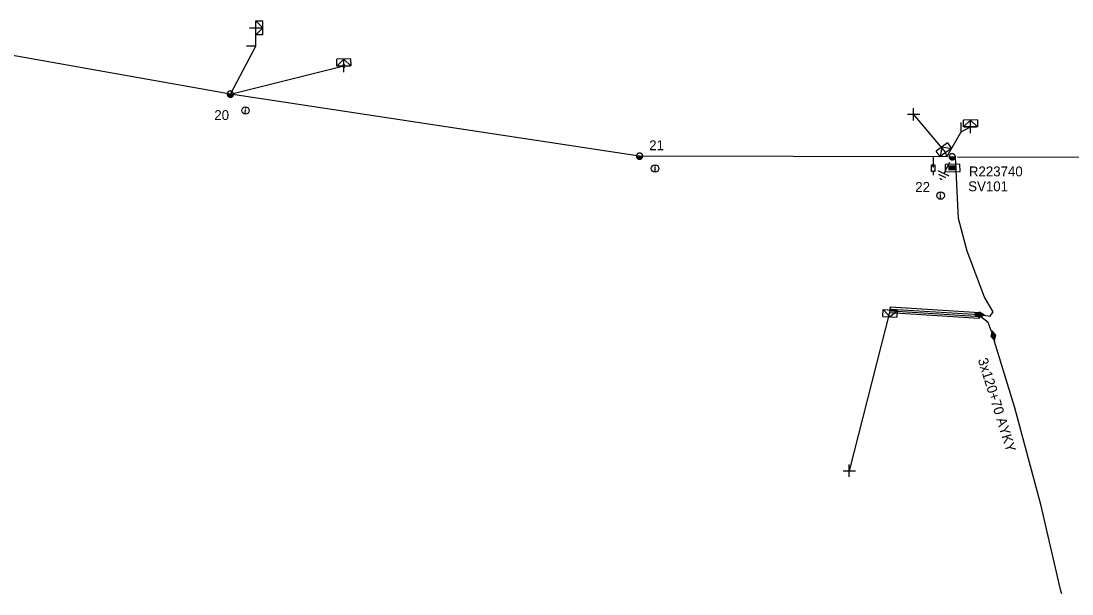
# Model space of a CAD drawing. Extents: x -544780 to -541582, y -1198995 to -1196551.
# Drawn here: x -541850 to -541744, y -1198987.6 to -1198929.8 of the extents above; entities that cross this region are included whole.
import ezdxf

# ---------------------------------------------------------------- set-up
doc = ezdxf.new("R2010")
doc.units = 0
for name, color, linetype in [('Vrstva 1', 7, 'Continuous'), ('Vrstva 10', 7, 'Continuous'), ('Vrstva 13', 7, 'Continuous'), ('Vrstva 14', 7, 'Continuous'), ('Vrstva 15', 7, 'Continuous'), ('Vrstva 16', 7, 'Continuous'), ('Vrstva 19', 7, 'Continuous'), ('Vrstva 2', 7, 'Continuous'), ('Vrstva 20', 7, 'Continuous'), ('Vrstva 28', 7, 'Continuous'), ('Vrstva 29', 7, 'Continuous'), ('Vrstva 30', 7, 'Continuous'), ('Vrstva 31', 7, 'Continuous'), ('Vrstva 34', 7, 'Continuous'), ('Vrstva 36', 7, 'Continuous'), ('Vrstva 4', 7, 'Continuous'), ('Vrstva 5', 7, 'Continuous'), ('Vrstva 54', 7, 'Continuous'), ('Vrstva 59', 7, 'Continuous'), ('Vrstva 6', 7, 'Continuous'), ('Vrstva 8', 7, 'Continuous'), ('Vrstva 9', 7, 'Continuous')]:
    doc.layers.add(name, color=color, linetype=linetype)

# ---------------------------------------------------------------- blocks, each defined once
blk = doc.blocks.new('NN440')
at = {"layer": 'Vrstva 2'}
for points in [[(0.63, 0), (0.63, 0.06), (0.62, 0.13), (0.6, 0.19), (0.58, 0.25), (0.55, 0.31), (0.51, 0.37), (0.47, 0.42), (0.42, 0.46), (0.37, 0.51), (0.32, 0.54), (0.26, 0.57), (0.2, 0.59), (0.13, 0.61), (0.07, 0.62), (0, 0.63), (-0.06, 0.62), (-0.13, 0.61), (-0.19, 0.59), (-0.26, 0.57), (-0.31, 0.54), (-0.37, 0.51), (-0.42, 0.46), (-0.47, 0.42), (-0.51, 0.37), (-0.54, 0.31), (-0.57, 0.25), (-0.6, 0.19), (-0.62, 0.13), (-0.63, 0.06), (-0.63, 0), (-0.63, -0.07), (-0.62, -0.14), (-0.6, -0.2), (-0.57, -0.26), (-0.54, -0.32), (-0.51, -0.37), (-0.47, -0.43), (-0.42, -0.47), (-0.37, -0.51), (-0.31, -0.55), (-0.26, -0.58), (-0.19, -0.6), (-0.13, -0.62), (-0.06, -0.63), (0, -0.63), (0.07, -0.63), (0.13, -0.62), (0.2, -0.6), (0.26, -0.58), (0.32, -0.55), (0.37, -0.51), (0.42, -0.47), (0.47, -0.43), (0.51, -0.37), (0.55, -0.32), (0.58, -0.26), (0.6, -0.2), (0.62, -0.14), (0.63, -0.07), (0.63, 0)], [(-0.63, 0), (0.63, 0)], [(-0.6, -0.18), (0.57, -0.18)], [(-0.51, -0.32), (0.5, -0.32)], [(-0.37, -0.47), (0.35, -0.47)]]:
    blk.add_lwpolyline(points, dxfattribs=at)
blk = doc.blocks.new('NN770')
at = {"layer": 'Vrstva 10'}
for p, q in [((0, 0.19), (0, 0.26)), ((0, -0.28), (0, 0.11))]:
    blk.add_line(p, q, dxfattribs=at)
blk.add_circle((0, -0.01), 0.375, dxfattribs=at)
blk = doc.blocks.new('NN870')
at = {"layer": 'Vrstva 4'}
for points in [[(0, -0.25), (0.5, 0), (0, 0.25), (-0.5, 0), (0, -0.25)], [(0.37, 0), (0, 0.19), (-0.36, 0), (0, -0.19), (0.37, 0)], [(0.24, 0), (0, 0.12), (-0.25, 0), (0, -0.12), (0.24, 0)], [(0.12, 0), (0, 0.06), (-0.13, 0), (0, -0.06), (0.12, 0)]]:
    blk.add_lwpolyline(points, dxfattribs=at)
blk = doc.blocks.new('NN800')
at = {"layer": 'Vrstva 1'}
for points in [[(-0.44, 0.44), (0.44, -0.44)], [(-0.44, -0.44), (0.44, 0.44)]]:
    blk.add_lwpolyline(points, dxfattribs=at)
blk = doc.blocks.new('NN820')
at = {"layer": 'Vrstva 13'}
for points in [[(0, 0), (0, -1.05)], [(-0.16, -0.81), (0.16, -0.81)], [(-0.16, -1.47), (-0.16, -0.81)], [(0, -1.05), (-0.06, -0.93)], [(0, -1.05), (0.06, -0.93)], [(0.16, -0.81), (0.16, -1.47)], [(0.16, -1.47), (-0.16, -1.47)], [(0, -1.47), (0, -1.87)]]:
    blk.add_lwpolyline(points, dxfattribs=at)
blk = doc.blocks.new('NN620')
at = {"layer": 'Vrstva 8'}
for points in [[(0.75, 0), (-0.75, 0)], [(-0.75, 0), (-0.75, -0.75)], [(0.75, -0.75), (0.75, 0)], [(-0.75, -0.75), (0.75, -0.75)], [(0.37, -0.18), (-0.38, -0.18)], [(-0.38, -0.18), (-0.38, -0.56)], [(-0.38, -0.56), (0.37, -0.56)], [(0.32, -0.23), (-0.33, -0.23)], [(-0.33, -0.23), (-0.33, -0.51)], [(-0.33, -0.51), (0.32, -0.51)], [(0.27, -0.27), (-0.28, -0.27)], [(-0.28, -0.27), (-0.28, -0.46)], [(-0.28, -0.46), (0.27, -0.46)], [(0.23, -0.32), (-0.23, -0.32)], [(-0.23, -0.32), (-0.23, -0.42)], [(-0.23, -0.42), (0.23, -0.42)], [(-0.19, -0.37), (0.19, -0.37)], [(0.23, -0.42), (0.23, -0.32)], [(0.27, -0.46), (0.27, -0.27)], [(0.32, -0.51), (0.32, -0.23)], [(0.37, -0.56), (0.37, -0.18)]]:
    blk.add_lwpolyline(points, dxfattribs=at)
blk = doc.blocks.new('NN630')
at = {"layer": 'Vrstva 9'}
for points in [[(0, -0.7), (-0.7, 0)], [(-0.7, -0.7), (-0.7, 0), (0.7, 0), (0.7, -0.7)], [(-0.7, -0.7), (0.7, -0.7)], [(0, -0.7), (0.7, 0)]]:
    blk.add_lwpolyline(points, dxfattribs=at)
blk = doc.blocks.new('NN810')
at = {"layer": 'Vrstva 14'}
for points in [[(0, -0.64), (0, -1.89)], [(0.63, -1.89), (-0.62, -1.89)], [(0.39, -2.2), (-0.4, -2.2)], [(0, -2.52), (-0.12, -2.52)], [(0.14, -2.52), (0, -2.52)]]:
    blk.add_lwpolyline(points, dxfattribs=at)
blk = doc.blocks.new('NN500')
at = {"layer": 'Vrstva 2'}
for points in [[(0, -0.24), (0.02, -0.23), (0.05, -0.23), (0.07, -0.22), (0.09, -0.22), (0.12, -0.2), (0.14, -0.19), (0.16, -0.18), (0.17, -0.16), (0.19, -0.14), (0.2, -0.12), (0.21, -0.1), (0.22, -0.07), (0.23, -0.05), (0.23, -0.02), (0.23, 0), (0.23, 0.02), (0.23, 0.05), (0.22, 0.07), (0.21, 0.1), (0.2, 0.12), (0.19, 0.14), (0.17, 0.16), (0.16, 0.17), (0.14, 0.19), (0.12, 0.2), (0.09, 0.21), (0.07, 0.22), (0.05, 0.23), (0.02, 0.23), (0, 0.23), (-0.03, 0.23), (-0.05, 0.23), (-0.07, 0.22), (-0.1, 0.21), (-0.12, 0.2), (-0.14, 0.19), (-0.16, 0.17), (-0.18, 0.16), (-0.19, 0.14), (-0.2, 0.12), (-0.22, 0.1), (-0.22, 0.07), (-0.23, 0.05), (-0.23, 0.02), (-0.24, 0), (-0.23, -0.02), (-0.23, -0.05), (-0.22, -0.07), (-0.22, -0.1), (-0.2, -0.12), (-0.19, -0.14), (-0.18, -0.16), (-0.16, -0.18), (-0.14, -0.19), (-0.12, -0.2), (-0.1, -0.22), (-0.07, -0.22), (-0.05, -0.23), (-0.03, -0.23), (0, -0.24)], [(0, -0.24), (0.02, -0.23), (0.05, -0.23), (0.07, -0.22), (0.09, -0.22), (0.12, -0.2), (0.14, -0.19), (0.16, -0.18), (0.17, -0.16), (0.19, -0.14), (0.2, -0.12), (0.21, -0.1), (0.22, -0.07), (0.23, -0.05), (0.23, -0.02), (0.23, 0), (0.23, 0.02), (0.23, 0.05), (0.22, 0.07), (0.21, 0.1), (0.2, 0.12), (0.19, 0.14), (0.17, 0.16), (0.16, 0.17), (0.14, 0.19), (0.12, 0.2), (0.09, 0.21), (0.07, 0.22), (0.05, 0.23), (0.02, 0.23), (0, 0.23), (-0.03, 0.23), (-0.05, 0.23), (-0.07, 0.22), (-0.1, 0.21), (-0.12, 0.2), (-0.14, 0.19), (-0.16, 0.17), (-0.18, 0.16), (-0.19, 0.14), (-0.2, 0.12), (-0.22, 0.1), (-0.22, 0.07), (-0.23, 0.05), (-0.23, 0.02), (-0.24, 0), (-0.23, -0.02), (-0.23, -0.05), (-0.22, -0.07), (-0.22, -0.1), (-0.2, -0.12), (-0.19, -0.14), (-0.18, -0.16), (-0.16, -0.18), (-0.14, -0.19), (-0.12, -0.2), (-0.1, -0.22), (-0.07, -0.22), (-0.05, -0.23), (-0.03, -0.23), (0, -0.24)], [(0, -0.21), (0.02, -0.2), (0.04, -0.2), (0.06, -0.2), (0.08, -0.19), (0.1, -0.18), (0.12, -0.17), (0.14, -0.15), (0.15, -0.14), (0.16, -0.12), (0.18, -0.1), (0.19, -0.08), (0.19, -0.06), (0.2, -0.04), (0.2, -0.02), (0.2, 0), (0.2, 0.02), (0.2, 0.04), (0.19, 0.06), (0.19, 0.08), (0.18, 0.1), (0.16, 0.12), (0.15, 0.14), (0.14, 0.15), (0.12, 0.17), (0.1, 0.18), (0.08, 0.19), (0.06, 0.19), (0.04, 0.2), (0.02, 0.2), (0, 0.2), (-0.02, 0.2), (-0.04, 0.2), (-0.06, 0.19), (-0.08, 0.19), (-0.1, 0.18), (-0.12, 0.17), (-0.14, 0.15), (-0.15, 0.14), (-0.17, 0.12), (-0.18, 0.1), (-0.19, 0.08), (-0.2, 0.06), (-0.2, 0.04), (-0.21, 0.02), (-0.21, 0), (-0.21, -0.02), (-0.2, -0.04), (-0.2, -0.06), (-0.19, -0.08), (-0.18, -0.1), (-0.17, -0.12), (-0.15, -0.14), (-0.14, -0.15), (-0.12, -0.17), (-0.1, -0.18), (-0.08, -0.19), (-0.06, -0.2), (-0.04, -0.2), (-0.02, -0.2), (0, -0.21)], [(0, -0.18), (0.02, -0.18), (0.04, -0.17), (0.05, -0.17), (0.07, -0.16), (0.09, -0.15), (0.1, -0.14), (0.12, -0.13), (0.13, -0.12), (0.14, -0.1), (0.15, -0.09), (0.16, -0.07), (0.17, -0.05), (0.17, -0.04), (0.17, -0.02), (0.17, 0), (0.17, 0.02), (0.17, 0.04), (0.17, 0.05), (0.16, 0.07), (0.15, 0.09), (0.14, 0.1), (0.13, 0.12), (0.12, 0.13), (0.1, 0.14), (0.09, 0.15), (0.07, 0.16), (0.05, 0.17), (0.04, 0.17), (0.02, 0.17), (0, 0.18), (-0.02, 0.17), (-0.04, 0.17), (-0.06, 0.17), (-0.07, 0.16), (-0.09, 0.15), (-0.1, 0.14), (-0.12, 0.13), (-0.13, 0.12), (-0.14, 0.1), (-0.15, 0.09), (-0.16, 0.07), (-0.17, 0.05), (-0.17, 0.04), (-0.18, 0.02), (-0.18, 0), (-0.18, -0.02), (-0.17, -0.04), (-0.17, -0.05), (-0.16, -0.07), (-0.15, -0.09), (-0.14, -0.1), (-0.13, -0.12), (-0.12, -0.13), (-0.1, -0.14), (-0.09, -0.15), (-0.07, -0.16), (-0.06, -0.17), (-0.04, -0.17), (-0.02, -0.18), (0, -0.18)], [(0, -0.15), (0.01, -0.15), (0.03, -0.14), (0.04, -0.14), (0.06, -0.13), (0.07, -0.13), (0.08, -0.12), (0.1, -0.11), (0.11, -0.1), (0.12, -0.09), (0.13, -0.07), (0.13, -0.06), (0.14, -0.05), (0.14, -0.03), (0.14, -0.02), (0.14, 0), (0.14, 0.01), (0.14, 0.03), (0.14, 0.04), (0.13, 0.06), (0.13, 0.07), (0.12, 0.09), (0.11, 0.1), (0.1, 0.11), (0.08, 0.12), (0.07, 0.13), (0.06, 0.13), (0.04, 0.14), (0.03, 0.14), (0.01, 0.14), (0, 0.15), (-0.02, 0.14), (-0.03, 0.14), (-0.05, 0.14), (-0.06, 0.13), (-0.07, 0.13), (-0.09, 0.12), (-0.1, 0.11), (-0.11, 0.1), (-0.12, 0.09), (-0.13, 0.07), (-0.13, 0.06), (-0.14, 0.04), (-0.14, 0.03), (-0.15, 0.01), (-0.15, 0), (-0.15, -0.02), (-0.14, -0.03), (-0.14, -0.05), (-0.13, -0.06), (-0.13, -0.07), (-0.12, -0.09), (-0.11, -0.1), (-0.1, -0.11), (-0.09, -0.12), (-0.07, -0.13), (-0.06, -0.13), (-0.05, -0.14), (-0.03, -0.14), (-0.02, -0.15), (0, -0.15)], [(0, -0.12), (0.01, -0.12), (0.02, -0.11), (0.03, -0.11), (0.05, -0.11), (0.06, -0.1), (0.07, -0.09), (0.08, -0.09), (0.09, -0.08), (0.09, -0.07), (0.1, -0.06), (0.11, -0.05), (0.11, -0.04), (0.11, -0.02), (0.11, -0.01), (0.12, 0), (0.11, 0.01), (0.11, 0.02), (0.11, 0.04), (0.11, 0.05), (0.1, 0.06), (0.09, 0.07), (0.09, 0.08), (0.08, 0.09), (0.07, 0.09), (0.06, 0.1), (0.05, 0.11), (0.03, 0.11), (0.02, 0.11), (0.01, 0.12), (0, 0.12), (-0.01, 0.12), (-0.03, 0.11), (-0.04, 0.11), (-0.05, 0.11), (-0.06, 0.1), (-0.07, 0.09), (-0.08, 0.09), (-0.09, 0.08), (-0.1, 0.07), (-0.1, 0.06), (-0.11, 0.05), (-0.11, 0.04), (-0.12, 0.02), (-0.12, 0.01), (-0.12, 0), (-0.12, -0.01), (-0.12, -0.02), (-0.11, -0.04), (-0.11, -0.05), (-0.1, -0.06), (-0.1, -0.07), (-0.09, -0.08), (-0.08, -0.09), (-0.07, -0.09), (-0.06, -0.1), (-0.05, -0.11), (-0.04, -0.11), (-0.03, -0.11), (-0.01, -0.12), (0, -0.12)], [(0, -0.09), (0.01, -0.09), (0.02, -0.09), (0.03, -0.08), (0.03, -0.08), (0.04, -0.08), (0.05, -0.07), (0.06, -0.07), (0.06, -0.06), (0.07, -0.05), (0.07, -0.04), (0.08, -0.04), (0.08, -0.03), (0.08, -0.02), (0.09, -0.01), (0.09, 0), (0.09, 0.01), (0.08, 0.02), (0.08, 0.03), (0.08, 0.03), (0.07, 0.04), (0.07, 0.05), (0.06, 0.06), (0.06, 0.06), (0.05, 0.07), (0.04, 0.07), (0.03, 0.08), (0.03, 0.08), (0.02, 0.08), (0.01, 0.09), (0, 0.09), (-0.01, 0.09), (-0.02, 0.08), (-0.03, 0.08), (-0.04, 0.08), (-0.04, 0.07), (-0.05, 0.07), (-0.06, 0.06), (-0.07, 0.06), (-0.07, 0.05), (-0.08, 0.04), (-0.08, 0.03), (-0.08, 0.03), (-0.09, 0.02), (-0.09, 0.01), (-0.09, 0), (-0.09, -0.01), (-0.09, -0.02), (-0.08, -0.03), (-0.08, -0.04), (-0.08, -0.04), (-0.07, -0.05), (-0.07, -0.06), (-0.06, -0.07), (-0.05, -0.07), (-0.04, -0.08), (-0.04, -0.08), (-0.03, -0.08), (-0.02, -0.09), (-0.01, -0.09), (0, -0.09)], [(0, -0.06), (0, -0.06), (0.01, -0.06), (0.02, -0.05), (0.02, -0.05), (0.03, -0.05), (0.03, -0.05), (0.04, -0.04), (0.04, -0.04), (0.05, -0.03), (0.05, -0.03), (0.05, -0.02), (0.05, -0.02), (0.05, -0.01), (0.06, -0.01), (0.06, 0), (0.06, 0.01), (0.05, 0.01), (0.05, 0.02), (0.05, 0.02), (0.05, 0.03), (0.05, 0.03), (0.04, 0.04), (0.04, 0.04), (0.03, 0.05), (0.03, 0.05), (0.02, 0.05), (0.02, 0.05), (0.01, 0.06), (0, 0.06), (0, 0.06), (-0.01, 0.06), (-0.01, 0.06), (-0.02, 0.05), (-0.02, 0.05), (-0.03, 0.05), (-0.03, 0.05), (-0.04, 0.04), (-0.04, 0.04), (-0.05, 0.03), (-0.05, 0.03), (-0.05, 0.02), (-0.06, 0.02), (-0.06, 0.01), (-0.06, 0.01), (-0.06, 0), (-0.06, -0.01), (-0.06, -0.01), (-0.06, -0.02), (-0.05, -0.02), (-0.05, -0.03), (-0.05, -0.03), (-0.04, -0.04), (-0.04, -0.04), (-0.03, -0.05), (-0.03, -0.05), (-0.02, -0.05), (-0.02, -0.05), (-0.01, -0.06), (-0.01, -0.06), (0, -0.06)], [(0, -0.03), (0, -0.03), (0, -0.03), (0.01, -0.03), (0.01, -0.03), (0.01, -0.02), (0.02, -0.02), (0.02, -0.02), (0.02, -0.02), (0.02, -0.02), (0.02, -0.01), (0.02, -0.01), (0.03, -0.01), (0.03, -0.01), (0.03, 0), (0.03, 0), (0.03, 0), (0.03, 0.01), (0.03, 0.01), (0.02, 0.01), (0.02, 0.01), (0.02, 0.02), (0.02, 0.02), (0.02, 0.02), (0.02, 0.02), (0.01, 0.02), (0.01, 0.02), (0.01, 0.03), (0, 0.03), (0, 0.03), (0, 0.03), (0, 0.03), (-0.01, 0.03), (-0.01, 0.03), (-0.01, 0.02), (-0.02, 0.02), (-0.02, 0.02), (-0.02, 0.02), (-0.02, 0.02), (-0.02, 0.02), (-0.03, 0.01), (-0.03, 0.01), (-0.03, 0.01), (-0.03, 0.01), (-0.03, 0), (-0.03, 0), (-0.03, 0), (-0.03, -0.01), (-0.03, -0.01), (-0.03, -0.01), (-0.03, -0.01), (-0.02, -0.02), (-0.02, -0.02), (-0.02, -0.02), (-0.02, -0.02), (-0.02, -0.02), (-0.01, -0.03), (-0.01, -0.03), (-0.01, -0.03), (0, -0.03), (0, -0.03)], [(0.23, 0), (0.7, 0)]]:
    blk.add_lwpolyline(points, dxfattribs=at)
blk = doc.blocks.new('NN510')
at = {"layer": 'Vrstva 2'}
blk.add_lwpolyline([(0, 0), (0, 0.94)], dxfattribs=at)

msp = doc.modelspace()

# ---------------------------------------------------------------- linework, layer by layer
at = {"layer": 'Vrstva 1'}
for points in [[(-541756.59, -1198943.46), (-541787.59, -1198943.4), (-541828.87, -1198937.14), (-541859.19, -1198931.74)], [(-541755.51, -1198943.46), (-541714.92, -1198943.58)]]:
    msp.add_lwpolyline(points, dxfattribs=at)
at = {"layer": 'Vrstva 20'}
msp.add_lwpolyline([(-541762.29, -1198958.62), (-541753.29, -1198959.19), (-541753.33, -1198959.79), (-541762.33, -1198959.22)], close=True, dxfattribs=at)
at = {"layer": 'Vrstva 5'}
for points in [[(-541753.3, -1198959.39), (-541752.22, -1198959.55), (-541751.92, -1198959.1), (-541752.78, -1198957.63), (-541754.55, -1198952.98), (-541755.43, -1198949.7), (-541755.71, -1198943.46)], [(-541751.91, -1198961.52), (-541752.43, -1198960.2), (-541753.18, -1198959.6), (-541762.19, -1198959.03), (-541762.31, -1198958.92), (-541762.19, -1198958.83), (-541753.3, -1198959.39)], [(-541745, -1198987.59), (-541745.12, -1198987.15), (-541747.07, -1198978.69), (-541749.72, -1198968.79), (-541751.69, -1198962.45), (-541751.91, -1198961.52)]]:
    msp.add_lwpolyline(points, dxfattribs=at)
at = {"layer": 'Vrstva 54'}
for points in [[(-541828.87, -1198937.14), (-541826.3, -1198932.28), (-541826.31, -1198930.45)], [(-541828.87, -1198937.14), (-541817.42, -1198934.29)], [(-541756.59, -1198943.46), (-541756.69, -1198943.03)]]:
    msp.add_lwpolyline(points, dxfattribs=at)
at = {"layer": 'Vrstva 59'}
for points in [[(-541756.69, -1198943.03), (-541759.95, -1198939.17)], [(-541762.31, -1198958.92), (-541766.44, -1198975.15)]]:
    msp.add_lwpolyline(points, dxfattribs=at)
at = {"layer": 'Vrstva 8'}
msp.add_lwpolyline([(-541756.59, -1198943.46), (-541755.14, -1198940.93), (-541754.21, -1198940.45)], dxfattribs=at)

# ---------------------------------------------------------------- block references
at = {"layer": 'Vrstva 13'}
for p, rotation in [((-541826.3, -1198932.28), 90.13152217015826), ((-541755.14, -1198940.93), 0.23913053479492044)]:
    msp.add_blockref('NN510', p, dxfattribs=dict(at, rotation=rotation))
for name, p, xscale, yscale, rotation in [('NN500', (-541817.42, -1198934.29), 0.5000000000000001, 0.4999999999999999, 91.73699998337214), ('NN440', (-541828.87, -1198937.14), 0.5, 0.5000000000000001, -8.62305003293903), ('NN440', (-541787.59, -1198943.4), 0.5000000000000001, 0.5, -0.10899718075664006), ('NN440', (-541756.05, -1198943.46), 0.5000000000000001, 0.4999999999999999, -0.16716392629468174)]:
    msp.add_blockref(name, p, dxfattribs=dict(at, xscale=xscale, yscale=yscale, rotation=rotation))
at = {"layer": 'Vrstva 15', "rotation": -26.91583339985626}
msp.add_blockref('NN810', (-541756.05, -1198943.46), dxfattribs=at)
at = {"layer": 'Vrstva 16', "rotation": -0.10899718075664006}
msp.add_blockref('NN820', (-541757.97, -1198943.46), dxfattribs=at)
at = {"layer": 'Vrstva 19'}
for p, rotation in [((-541753.3, -1198959.39), -3.626527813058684), ((-541751.91, -1198961.52), -76.69082219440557)]:
    msp.add_blockref('NN870', p, dxfattribs=dict(at, rotation=rotation))
at = {"layer": 'Vrstva 28', "rotation": 1.5560000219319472}
msp.add_blockref('NN620', (-541756.03, -1198944.21), dxfattribs=at)
at = {"layer": 'Vrstva 31'}
for p, rotation in [((-541826.31, -1198930.45), 90.13152223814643), ((-541817.42, -1198934.29), -178.2631276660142), ((-541754.21, -1198940.45), -179.7608694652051), ((-541756.69, -1198943.03), -143.7332028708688), ((-541762.31, -1198958.92), -3.6482860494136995)]:
    msp.add_blockref('NN630', p, dxfattribs=dict(at, rotation=rotation))
at = {"layer": 'Vrstva 34'}
for p, rotation in [((-541826.31, -1198930.45), 45), ((-541817.42, -1198934.29), 45.00000009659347), ((-541759.95, -1198939.17), 45), ((-541754.21, -1198940.45), 45), ((-541766.44, -1198975.15), 44.99999995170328)]:
    msp.add_blockref('NN800', p, dxfattribs=dict(at, rotation=rotation))
at = {"layer": 'Vrstva 36'}
for p, rotation in [((-541827.35, -1198938.78), -8.62305003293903), ((-541786.03, -1198944.63), -0.1089973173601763), ((-541757.22, -1198947.37), -0.16716392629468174)]:
    msp.add_blockref('NN770', p, dxfattribs=dict(at, rotation=rotation))

# ---------------------------------------------------------------- texts
at = {"layer": 'Vrstva 14'}
for s, p in [('20', (-541830.49, -1198939.75)), ('21', (-541786.62, -1198942.8)), ('22', (-541759.78, -1198947.01))]:
    msp.add_text(s, height=1, dxfattribs=at).set_placement(p)
at = {"layer": 'Vrstva 29'}
msp.add_text('R223740', height=1, dxfattribs=at).set_placement((-541754.37, -1198945.44))
at = {"layer": 'Vrstva 30'}
msp.add_text('SV101', height=1, dxfattribs=at).set_placement((-541754.44, -1198946.94))
at = {"layer": 'Vrstva 6'}
msp.add_text('3x120+70 AYKY', height=1, rotation=287.261, dxfattribs=at).set_placement((-541753.48, -1198963.94))

doc.saveas('drawing.dxf')
